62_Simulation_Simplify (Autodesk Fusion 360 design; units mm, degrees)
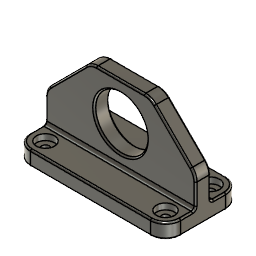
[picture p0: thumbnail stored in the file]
part number: 2026-07-20-13-25-26-316
sketch "Sketch1" plane through (0, 0, 0) normal (0, 1, 0) x axis (1, 0, 0)
  line L1 (-50, 25) -> (50, 25)
  line L2 (-50, -25) -> (-50, 25)
  line L3 (50, -25) -> (-50, -25)
  line L4 (50, 25) -> (50, -25)
  line L5 (-50, -25) -> (50, 25)
  line L6 (50, -25) -> (-50, 25)
  point P6 (0, 0)
  point P1 (0, 0)
  point P4 (-50, -25)
  point P5 (50, -25)
  point P3 (-50, 25)
  horizontal L1
  perpendicular L1 L2
  parallel L1 L3
  parallel L2 L4
  coincident L5 P6
  coincident L6 P6
  coincident P1 P6
  dimension "d2" distance P4 P5 = 100
  dimension "d3" distance P3 P4 = 50
extrude "Extrude1" new body sketch "Sketch1" profile of L1 L2 L3 L4 distance 10
sketch "Sketch2" plane through (0, 0, -25) normal (0, 0, -1) x axis (1, 0, 0)
  line L1 (-50, -5) -> (-50, 5)
  line L2 (50, -5) -> (-50, -5)
  line L3 (50, 5) -> (50, -5)
  line L4 (-50, 5) -> (50, 5)
  line L5 (-50, -25) -> (50, -25)
  line L6 (-50, 25) -> (-50, -25)
  line L7 (50, 25) -> (-50, 25)
  line L8 (50, -25) -> (50, 25)
  line L9 (-50, 25) -> (50, -25)
  line L10 (50, 25) -> (-50, -25)
  point P10 (0, 0)
  point P1 (0, 0)
  point P5 (50, 5)
  point P7 (-50, -25)
  point P8 (-50, 25)
  horizontal L5
  perpendicular L5 L6
  parallel L5 L7
  parallel L6 L8
  coincident L9 P10
  coincident L10 P10
  coincident P1 P10
  coincident P5 L8
  dimension "d6" distance P7 P8 = 50
extrude "Extrude2" add sketch "Sketch2" profile of L1 L2 L3 L4 L5 L6 L7 L8 along normal blind 10
chamfer "Chamfer1" sketch "Sketch2" distance 30
sketch "Sketch3" plane through (0, -5, 0) normal (0, -1, 0) x axis (1, 0, 0)
  line L1 (20, 25) -> (50, -5)
  line L2 (-20, 25) -> (20, 25)
  line L3 (-50, -5) -> (-20, 25)
  line L4 (-50, -25) -> (-50, -5)
  line L5 (50, -25) -> (-50, -25)
  line L6 (50, -5) -> (50, -25)
  circle C1 centre (0, 0) radius 17.5
  point P1 (0, 0)
  point P8 (0, 0)
  coincident P1 P8
  dimension "d10" diameter C1 = 35
extrude "Extrude3" cut sketch "Sketch3" profile of C1 no distance stored
fillet "Fillet1" radius 10
fillet "Fillet2" radius 10
sketch "Sketch4" plane through (0, 0, -25) normal (0, 0, 1) x axis (-1, 0, 0)
  line L1 (50, -5) -> (50, -15)
  line L2 (-50, -5) -> (50, -5)
  line L3 (-50, -15) -> (-50, -5)
  line L4 (40, -25) -> (-40, -25)
  line L5 (-40, 25) -> (40, 25)
  line L6 (-50, 5) -> (-50, 15)
  line L7 (50, 5) -> (-50, 5)
  line L8 (50, 15) -> (50, 5)
  arc A1 centre (40, -15) radius 10 clockwise from (50, -15) to (40, -25)
  arc A2 centre (-40, -15) radius 10 clockwise from (-40, -25) to (-50, -15)
  arc A3 centre (40, 15) radius 10 clockwise from (40, 25) to (50, 15)
  arc A4 centre (-40, 15) radius 10 clockwise from (-50, 15) to (-40, 25)
  point P9 (-40, -15)
  point P18 (-40, -15)
  point P4 (40, -15)
  point P19 (40, -15)
  point P12 (40, 15)
  point P20 (40, 15)
  point P15 (-40, 15)
  point P21 (-40, 15)
  coincident P9 P18
  coincident P4 P19
  coincident P12 P20
  coincident P15 P21
hole "Hole1" sketch "Sketch2" HoleDiameter 5 TipAngle 118 CBDepth 4 CBDiameter 12
fillet "Fillet3" radius 2
fillet "Fillet4" radius 1
chamfer "Chamfer2" sketch "Sketch2" distance 1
